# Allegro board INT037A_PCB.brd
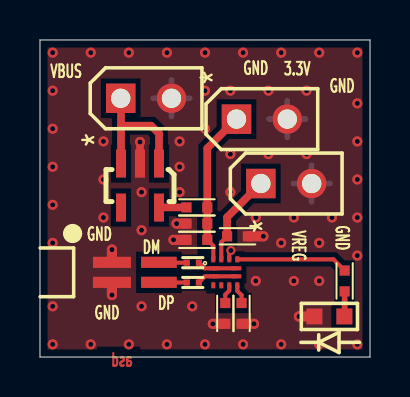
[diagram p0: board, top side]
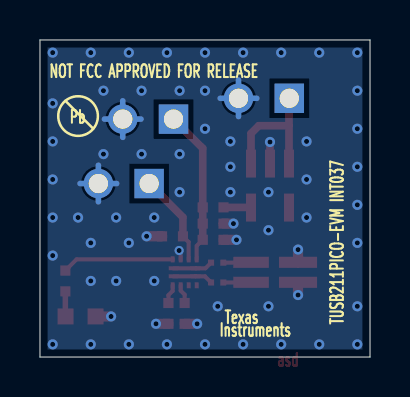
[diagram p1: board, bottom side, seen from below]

Outline 16.51 x 15.88 mm; copper layers: TOP, BOTTOM. Coordinates in mm from the lower left corner of the outline.
Outline path: 0,15.88 16.51,15.88 16.51,0 0,0 0,15.88

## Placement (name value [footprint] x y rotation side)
C1  0.01uF  [0402]  7.85 5.87 180 top
C2  0.1uF  [0402]  7.85 6.68 180 top
C3  0.1uF  [0402]  9.88 6.05 0 top
C4  0.1uF  [0402]  9.27 2.18 270 top
D1  Green  [LED_LTST-C190KGKT]  14.48 2.03 0 top
J1  SAMTEC_FTMH-102-03-L-DH  [HDR_SMRT_2X2_39_FTMH]  4.78 4.24 270 top
JMP1  Header 2x1  [HDR_THVT_1X2_100]  9.83 11.91 90 top
JMP2  Header 2x1  [HDR_THVT_1X2_100]  11.05 8.69 90 top
JMP3  Header 2x1  [HDR_THVT_1X2_100]  4.04 12.95 90 top
NOREF  -  []  -85.72 -69.85 0 top
NOREF#2  -  []  0 0 0 top
NOREF#3  -  []  6.99 38.1 0 top
NOREF#4  -  []  0 15.88 0 top
NOREF#5  -  []  16.51 0 90 top
NOREF#6  -  []  0 0 0 top
R1  3.9k  [0402]  10.08 2.18 270 top
R2  0 ohm  [0201]  7.65 4.72 0 top
R3  o ohm  [0201]  7.65 3.73 0 top
R4  0 ohm  [0402]  7.85 7.49 0 top
R5  75  [0402]  15.24 3.81 270 top
U1  TUSB211RWB  [RWB]  9.27 4.24 0 top
U2  LP5907  [DBV_R-PDSO-G5]  5 8.59 270 top

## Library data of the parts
C1-C4 = cc0402
D1 = Green LED
J1 = SAMTEC_HDR
JMP1-JMP3 = Header 2x1
R1 R4 R5 = r0402
R2 R3 = r0201
U1 = TUSB211RWB
U2 = LP5907

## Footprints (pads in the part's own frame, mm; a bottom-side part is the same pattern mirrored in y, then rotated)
0201
  rect 0.305x0.305 smd: 1(-0.305,0) 2(0.305,0)
0402
  rect 0.508x0.508 smd: 1(-0.521,0) 2(0.521,0)
DBV_R-PDSO-G5
  rect 1.4x0.5 smd: 1(-1.1,0.95) 2(-1.1,0) 3(-1.1,-0.95) 4(1.1,-0.95) 5(1.1,0.95)
HDR_SMRT_2X2_39_FTMH
  rect 0.559x1.905 smd: 1(-0.5,-1.175) 3(0.5,-1.175)
  rect 0.559x1.778 smd: 2(-0.5,1.175) 4(0.5,1.175)
HDR_THVT_1X2_100
  rect 1.473x1.473 hole 0.965: 1(0,0)
  round 1.473 hole 0.965: 2(0,-2.54)
LED_LTST-C190KGKT
  rect 0.8x0.8 smd: 1(-0.75,0) 2(0.75,0)
RWB
  rect 0.5x0.2 smd: 1(-0.55,0.2) 2(-0.55,-0.2) 7(0.55,-0.2) 8(0.55,0.2)
  rect 0.2x0.3 smd: 3(-0.6,-0.65) 4(-0.2,-0.65) 5(0.2,-0.65) 6(0.6,-0.65) 9(0.6,0.65) 10(0.2,0.65) 11(-0.2,0.65) 12(-0.6,0.65)

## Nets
GND: C1.2 C2.2 C3.2 C4.2 D1.1(CATHODE) J1.1 J1.3 JMP1.2 JMP2.2 JMP3.2 R1.2 U1.10(GND) U2.2(GND)
N00271: R3.2 U1.2(D1P) U1.7(D2P)
N00296: R2.2 U1.1(D1M) U1.8(D2M)
N00343: C3.1 JMP2.1 U1.11(VREG)
N00391: C1.1 C2.1 JMP1.1 R4.2 U1.12(VCC)
N00931: C4.1 U1.5(RSTN)
N00935: R1.1 U1.6(EQ)
N16589199: JMP3.1 U2.1(VIN) U2.3(EN)
N16589333: R4.1 U2.5(VOUT)
N16590097: J1.2 R2.1
N16590109: J1.4 R3.1
N16590469: R5.1 U1.9(ENA_HS)
N16590481: D1.2(ANODE) R5.2

Pads without a net: U1 3 4; U2 4

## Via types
v1: diameter 0.508, hole 0.254, TOP to BOTTOM, 65 vias
v2: diameter 0.457, hole 0.254, TOP to BOTTOM, 1 via

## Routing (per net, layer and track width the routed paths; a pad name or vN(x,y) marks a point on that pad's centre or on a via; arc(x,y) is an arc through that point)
GND: length 17.7
  TOP w0.203: U1.10 9.47,5.25 v2(9.55,5.33)
  TOP w0.381: U2.2 v1(5,10.77)
  TOP w0.508: C1.2 v1(6.68,5.87) ; J1.1 v1(3.6,5.38) ; C3.2 v1(11.18,6.05) ; J1.3 v1(3.6,3.11) ; R1.2 v1(10.71,1.66) ; C2.2 v1(6.83,6.68) ; D1.1 v1(12.95,2.03) ; C4.2 v1(8.65,1.66)
  BOTTOM w0.279: 5.66,12.95 JMP3.2 ; JMP3.2 6.58,12.04 ; JMP3.2 7.49,12.95 ; JMP3.2 6.58,13.87 ; JMP2.2 13.59,9.6 ; JMP2.2 13.59,7.77 ; JMP2.2 14.5,8.69 ; JMP2.2 12.67,8.69 ; JMP1.2 13.28,11.91 ; JMP1.2 12.37,11 ; JMP1.2 11.45,11.91 ; JMP1.2 12.37,12.83
  vias: v1(0.64,15.24) v1(0.64,13.34) v1(0.64,11.43) v1(0.64,9.53) v1(0.64,7.62) v1(0.64,5.71) v1(0.64,2.54) v1(0.64,0.64) v1(2.54,15.24) v1(2.54,0.64) v1(3.17,10.79) v1(3.17,8.89) v1(3.17,6.99) v1(4.45,15.24) v1(4.45,0.64) v1(5.08,8.26) v1(5.08,6.35) v1(5.08,2.54) v1(6.35,15.24) v1(6.35,0.64) v1(6.99,10.79) v1(6.99,9.53) v1(6.99,8.26) v1(7.62,2.54) v1(8.26,15.24) v1(8.26,13.34) v1(8.26,11.43) v1(8.26,0.64) v1(9.53,13.34) v1(9.53,10.16) v1(9.53,8.26) v1(10.16,15.24) v1(10.16,0.64) v1(10.79,6.99) v1(10.79,3.81) v1(11.43,13.34) v1(11.43,10.16) v1(12.06,15.24) v1(12.06,5.71) v1(12.06,0.64) v1(12.7,6.99) v1(12.7,3.81) v1(13.34,13.34) v1(13.34,10.16) v1(13.97,15.24) v1(13.97,5.71) v1(13.97,3.81) v1(13.97,0.64) v1(14.61,6.99) v1(15.88,15.24) v1(15.88,12.7) v1(15.88,10.79) v1(15.88,8.89) v1(15.88,6.99) v1(15.88,5.08) v1(15.88,0.64)
N00271: length 2
  TOP w0.203: U1.7 U1.2 8.26,4.04 R3.2
N00296: length 2
  TOP w0.203: R2.2 8.23,4.44 U1.1 U1.8
N00343: length 4.6
  TOP w0.203: U1.11 9.07,5.76 C3.1
  TOP w0.381: JMP2.1 9.36,7 C3.1
N00391: length 7.8
  TOP w0.203: U1.12 8.67,5.57 C1.1
  TOP w0.381: JMP1.1 8.37,10.45 R4.2 C2.1 C1.1
N00931: length 1
  TOP w0.203: U1.5 9.47,3.32 9.27,3.12 C4.1
N00935: length 1
  TOP w0.203: U1.6 9.87,3.31 10.08,3.1 R1.1
N16589199: length 6.8
  TOP w0.381: 4.05,11.58 5.56,11.58 5.95,11.19 U2.1 ; 4.05,11.58 4.05,12.94 JMP3.1 ; 4.05,11.58 U2.3
N16589333: length 1.4
  TOP w0.381: R4.1 5.96,7.49 U2.5
N16590097: length 1.4
  TOP w0.203: R2.1 5.97,4.72 J1.2
N16590109: length 1.4
  TOP w0.203: J1.4 5.96,3.73 R3.1
N16590469: length 5.6
  TOP w0.203: U1.9 14.68,4.89 R5.1
N16590481: length 1.3
  TOP w0.279: D1.2 15.24,2.04 R5.2

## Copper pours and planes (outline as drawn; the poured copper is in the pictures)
GND on TOP: 0.38,15.49 0.38,0.38 16.13,0.38 16.13,15.49 ; 1 cut-out
GND on BOTTOM: 0.38,0.38 0.38,15.49 16.13,15.49 16.13,0.38

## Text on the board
BOTTOM: LAYER 4 - BOTTOM SIDE
Board Geometry/Soldermask Bottom: SOLDERMASK BOTTOM
Package Geometry/Pastemask Bottom: PASTEMASK BOTTOM
Ref Des/Silkscreen Bottom: Texas | Instruments | Pb | NOT FCC APPROVED FOR RELEASE | TUSB211PICO-EVM INT037 | SILKSCREEN BOTTOM
TOP: asd | LAYER 1 - TOP SIDE
Board Geometry/Soldermask Top: SOLDERMASK TOP
Package Geometry/Pastemask Top: PASTEMASK TOP
Ref Des/Silkscreen Top: VBUS | GND | DM | DP | 3.3V | VREG | SILKSCREEN TOP
XSECTION_CHART: * AIR 0 MIL | * SOLDERMASK-0.8MIL 0.8 MIL | L1: COPPER_1/2OZ_PLATED 2 MIL | * CORE_1.50 56.4 MIL | L2: COPPER_1/2OZ_PLATED 2 MIL | DESIGN CROSS SECTION CHART | ___________________________ | TOTAL THICKNESS 62 MIL | 1-2
DIMENSION: FABRICATION DRAWING | CAD ORIGIN
User.6: LAYER 1 | LAYER 2 | LAYER 3 | LAYER 4 | LAYER | NO. | TABLE 1: | TOP | L2_GND | L3_PWR | BOTTOM | NAME | DIFFIRENTIAL PAIR | IMPEDANCE (OHMS) | 100 +/- 10% | 90  +/- 10% | DIFF TRACE | WIDTH | 0.0055" | 0.0048" | SPACING | 0.0045" | SINGLE ENDED | 50 +/- 10% | 45 +/- 10% | TRACE WIDTH | 0.0095" | 0.0115" | REFERENCE | SPECIAL FAB NOTES: | PLACE DRILL CHART HERE: | 1:FAB SHOP MUST FOLLOW THE SOLDER MASK REVIEW LAYERS. | 2:ALL BOARDS MUST MEET OR EXCEED UL94-V0 REQUIREMENTS. | MIN. ANNULAR RING 2 MIL EXTERNAL PER IPC-6012C CLASS 2 | REGISTRATION TOLERANCES: METAL +/- X MIL,HOLES +/- X MIL | IMPEDANCE CONTROL: | BOARD SIZE (REFER ALSO ARRAY/PANEL PROFILING INFORMATION) | MIXED DIELECTRIC: | LAMINATE MATERIAL: | THICKNESS: | TOLERANCE: | COPPER THICKNESS (FINISHED): | BOARD FINISH: | NUMBER OF LAYERS: | MIN. TRACK WIDTH: | MIN. CLEARANCE  : | MIN. VIA PAD/DRILL: | THIEVING ALLOWED: | X | OUTER: | INNER SIGNAL: | INNER PLANE: | OTHER: | SILKSCREEN: | SOLDERMASK: (PER IPC-6011,6012) | BOARD SURFACE TREATMENT: | ADDITIONAL REQUIREMENTS: | VENDOR MARKING: | SILKSCREEN COLOR: | SOLDERMASK COLOR: | THROUGH-HOLE VIA TREATMENT: | VIA FILL USING NON-CONDUCTIVE EPOXY: | FOR WIRE BONDING: | VENDOR DATE CODE,UL,LOGO: | FR-4 HIGH Tg | 0.062" +/-10% | IPC-6012C TYPE 3 CLASS 2 | OTHER +/- | MICRO-SECTION | CERTIFICATES OF COMPLIANCE | NICKEL/GOLD (ENIG) | IMMERSION TIN | HARD GOLD | IN AN OPEN AREA | 1/4 OZ. | OPEN | NO | 2 | 8.0 MIL | X.X MIL | 18/10 MIL | NONE | DESIGN INFORMATION | ROGERS 4350B | 0.093" +/-10% | YES | TDR REPORTS/COUPONS | WHITE | GREEN | SOFT GOLD | TENTED | 1/2 OZ. | BOW & TWIST: | ORGANIC (OSP) | OTHER | WHERE INDICATED (SEE DRAWING) | YES - SEE TABLE 1 | ETCH | IDENTIFIER: | BLUE | RoHS | 1.0 OZ. | SILKSCREEN | PER SUPPLIED ARTWORK | ALL x MIL VIAS | ELECTRICAL TEST | UL 94V-0 | HASL | 2.0 OZ. | BREAK-AWAY | ENEPIG | FIGURE | SIZE | 10.0 | 38.0 | DRILL CHART: TOP to BOTTOM | ALL UNITS ARE IN MILS | TOLERANCE | +3.0/-3.0 | PLATED | QTY | 66 | 6
